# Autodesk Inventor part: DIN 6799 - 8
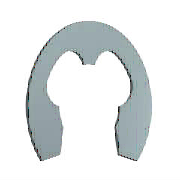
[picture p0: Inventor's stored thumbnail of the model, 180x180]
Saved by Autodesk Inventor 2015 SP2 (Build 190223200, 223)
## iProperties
Created: 2014-02
Part Number: DIN 6799 - 8
Material: Stahl, weich
Description: Sicherungsscheibe
Document SubType Name: Modeling
Standard: DIN 6799
Designer: rYan
Standards Organization: DIN
Language: de-DE
Size Designation: 8
Categories: <MemberInstance><Categories><Category DisplayName="Wellenteile" InternalName="7f7aeb1f-a693-4053-b835-cee3144e0d98" Mnemonic="SHFT"><Category DisplayName="Siche
Density: 7.85 g/cm^3
Appearance: Halbpoliert
IsCustomPart: 0
Author: rYan
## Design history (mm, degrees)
sketch "Skizze1"
  geometry: L1 (-0.8, 0.024)-(0, 0.024) reference; L2 (-3.206, 0)-(3.486, 0) reference; L3 (-3.666, -6.076)-(3.666, -6.076); L4 (0, 1.949)-(0, -3.479) reference; L5 (-4.8, -2.876)-(-4.016, -2.876); L6 (-0.8, 0.324)-(-0.8, 1.101); L7 (0, 3.674)-(2.53, 3.674); L8 (-3.666, -6.076)-(-4.668, -8.741); L9 (0, -0.476)-(-1.278, -0.476); L10 (3.666, -6.076)-(4.668, -8.741); L11 (4.8, -2.876)-(4.016, -2.876); L12 (0.8, 0.324)-(0.8, 1.101); C1 r 4.5 at (0, -4.476); A1 r 4 centre (0, -4.476) between (-3.789, -3.193) and (-3.666, -6.076); A2 r 0.8 centre (0, 0.324) between (-0.8, 0.324) and (0.8, 0.324); A3 r 8.15 centre (0, -4.476) between (6.791, -8.982) and (-6.791, -8.982); A4 r 6.4 centre (0, -4.476) between (-1.6, 1.72) and (-5.647, -1.465); A5 r 0.64 centre (-1.44, 1.101) between (-0.8, 1.101) and (-1.6, 1.72); A6 r 0.96 centre (-4.8, -1.916) between (-5.647, -1.465) and (-4.8, -2.876); A7 r 0.24 centre (-4.016, -3.116) between (-3.789, -3.193) and (-4.016, -2.876); A8 r 1.2 centre (-5.791, -8.319) between (-6.791, -8.982) and (-4.668, -8.741); A9 r 1.2 centre (5.791, -8.319) between (4.668, -8.741) and (6.791, -8.982); A10 r 4 centre (0, -4.476) between (3.666, -6.076) and (3.789, -3.193); A11 r 0.24 centre (4.016, -3.116) between (4.016, -2.876) and (3.789, -3.193); A12 r 0.96 centre (4.8, -1.916) between (4.8, -2.876) and (5.647, -1.465); A13 r 6.4 centre (0, -4.476) between (5.647, -1.465) and (1.6, 1.72); A14 r 0.64 centre (1.44, 1.101) between (1.6, 1.72) and (0.8, 1.101); 1 further point
  constraints: 30 point on circle, 20 end point, 15 centre point, 13 symmetric about line, 12 tangent, 8 point on line, 4 parallel, 2 coincident, 2 horizontal, 1 concentric, 1 perpendicular, 1 vertical alignment, 9 other
  dimensions: "d0" = 9 diameter of C1 (= WD); "d3" = 1.6 distance from line of A1.centre L3 (= 0.2 x ND); "d4" = 0.8 radius of A2 (= 0.1 x ND); "d5" = 16.3 diameter of A3 (= SD2); "d8" = 6.4 radius of A4 (= 0.8 x ND); "d9" = 1.6 distance from line of A1.centre L5 (= 0.2 x ND); "d10" = 0.64 radius of A5 (= 0.08 x ND); "d11" = 0.96 radius of A6 (= 0.12 x ND); "d12" = 0.24 radius of A7 (= 0.03 x ND); "d13" = 1.2 radius of A8 (= 0.15 x ND); "d14" = 4 distance from line of A1.centre L9 (= 0.5 x ND); "d15" = 4 radius of A1 (= 0.5 x ND)
extrude "Körper" new body sketch "Skizze1" distance "d16" = 1 (= SD); taper "d17" = 0 deg
workaxis "Work Axis1"
workaxis "Work Axis2"
workplane "Work Plane1"
body "Solid1"
other parameters: "ND" = 8 [user parameter; used in 14 equation terms], "SD" = 1 [user parameter; used in 1 equation term], "WD" = 9 [user parameter; used in 1 equation term], "d1" = 12.8 (= 1.6 x ND), "d2" = 8 (= ND), "SD2" = 16.3 [user parameter; used in 1 equation term], "d6" = 8 (= ND), "d7" = 1.2 (= 0.15 x ND), "d18" = 0, "d19" = 0, "d27" = 0, "d28" = 0, "WDMIN" = 8 [user parameter], "SNB" = 1.05 [user parameter], "WDMAX" = 11 [user parameter], "BUBRMI" = 1.5 [user parameter]
